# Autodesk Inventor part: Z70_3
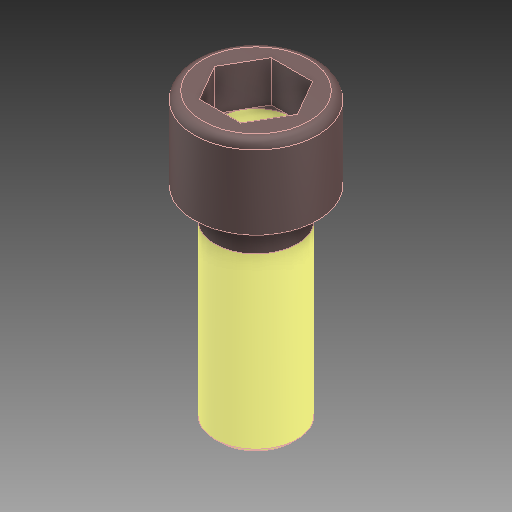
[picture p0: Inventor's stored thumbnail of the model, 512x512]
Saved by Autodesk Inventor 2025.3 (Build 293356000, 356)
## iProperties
Created: 2025-03
Part Number: Z70_3
Material: Všeobecné
Document SubType Name: Modeling
Designer: Patrik
Density: 1 g/cm^3
Appearance: Výchozí
Mass: 13.6463 g
Surface Area: 44.3902 cm^2
Volume: 13.6463 cm^3
Author: Patrik
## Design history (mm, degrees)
feature "Base1"
node "Těleso1"
